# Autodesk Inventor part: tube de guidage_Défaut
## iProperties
Shininess: 64.0
Length Units: 11269
Angle Units: 11279
Time Units: 11290
Mass Units: 11283
Length Display Precision: 3
Angle Display Precision: 2
Compacted: True
Part Number: tube de guidage_Défaut
Document SubType Name: Modeling
Created: 2006-11
Material: Par défaut
Designer: profs_sti
Density: 0.0
Volumn: 0.0
Area: 0.0
PropertySet Name: Model Information
Control State: 0
Master: False
Checked Out: False
Author: profs_sti
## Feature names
1. Base1
